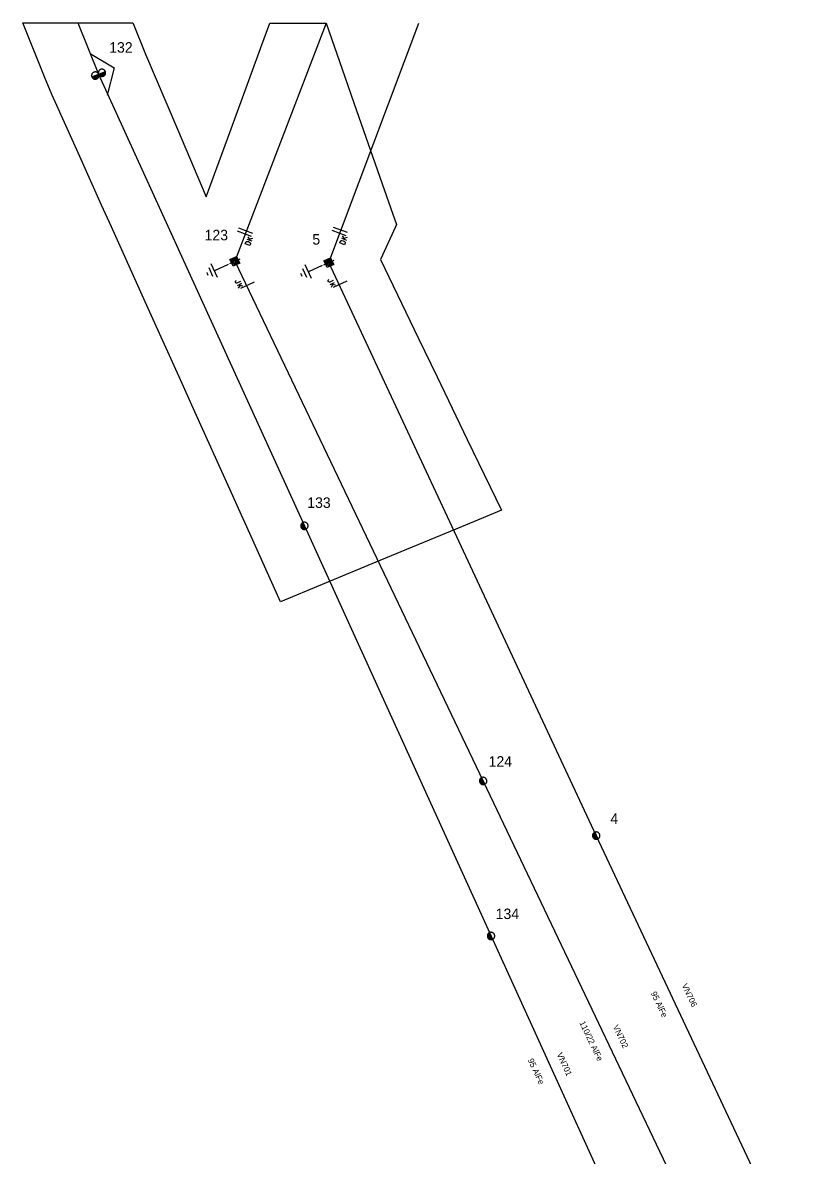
# Model space of a CAD drawing. Extents: x -536397 to -535454, y -1201642 to -1200953.
# Drawn here: x -536397 to -536267.9, y -1201142.3 to -1200953.5 of the extents above; entities that cross this region are included whole.
import ezdxf

# ---------------------------------------------------------------- set-up
doc = ezdxf.new("R2010")
doc.units = 0
for name, color, linetype in [('Vrstva 1', 7, 'Continuous'), ('Vrstva 13', 7, 'Continuous'), ('Vrstva 14', 7, 'Continuous'), ('Vrstva 15', 7, 'Continuous'), ('Vrstva 18', 7, 'Continuous'), ('Vrstva 2', 7, 'Continuous'), ('Vrstva 3', 7, 'Continuous'), ('Vrstva 35', 7, 'Continuous')]:
    doc.layers.add(name, color=color, linetype=linetype)

# ---------------------------------------------------------------- blocks, each defined once
blk = doc.blocks.new('VN850')
at = {"layer": 'Vrstva 15'}
for points in [[(-0.56, 1.43), (-0.56, -1.07)], [(-0.01, 1.43), (-0.01, -1.07)], [(-2.09, -0.54), (-1.78, -0.54)], [(-2.09, -1.41), (-2.09, -0.54)], [(-1.78, -1.41), (-2.09, -1.41)], [(-1.78, -0.54), (-1.66, -0.6)], [(-1.67, -1.35), (-1.78, -1.41)], [(-1.59, -1.2), (-1.67, -1.35)], [(-1.66, -0.6), (-1.59, -0.75)], [(-1.59, -0.75), (-1.55, -0.96)], [(-1.55, -0.96), (-1.59, -1.2)], [(-1.26, -0.54), (-1.26, -1.41)], [(-0.85, -0.54), (-1.26, -1.09)], [(-1.13, -0.92), (-0.77, -1.41)]]:
    blk.add_lwpolyline(points, dxfattribs=at)
blk = doc.blocks.new('VN840')
at = {"layer": 'Vrstva 15'}
for points in [[(-0.01, 1.41), (-0.01, -1.09)], [(-1.51, -1.24), (-1.51, -1.15)], [(-1.48, -1.35), (-1.51, -1.24)], [(-1.33, -1.42), (-1.48, -1.35)], [(-1.27, -1.42), (-1.33, -1.42)], [(-1.13, -1.35), (-1.27, -1.42)], [(-1.09, -1.24), (-1.13, -1.35)], [(-1.09, -0.59), (-1.09, -1.24)], [(-0.68, -0.59), (-0.68, -1.42)], [(-0.68, -1.11), (-0.27, -0.59)], [(-0.54, -0.94), (-0.2, -1.42)]]:
    blk.add_lwpolyline(points, dxfattribs=at)
blk = doc.blocks.new('VN860')
at = {"layer": 'Vrstva 15'}
for points in [[(-3.74, 0), (0.01, 2.82)], [(0.01, 2.82), (3.76, 0)]]:
    blk.add_lwpolyline(points, dxfattribs=at)
blk = doc.blocks.new('VN440')
at = {"layer": 'Vrstva 2'}
for points in [[(1.22, 0), (1.21, 0.13), (1.19, 0.25), (1.16, 0.38), (1.11, 0.5), (1.05, 0.61), (0.98, 0.72), (0.9, 0.82), (0.81, 0.91), (0.71, 0.99), (0.6, 1.06), (0.49, 1.12), (0.37, 1.16), (0.25, 1.2), (0.12, 1.22), (-0.01, 1.22), (-0.14, 1.22), (-0.26, 1.2), (-0.39, 1.16), (-0.51, 1.12), (-0.62, 1.06), (-0.73, 0.99), (-0.83, 0.91), (-0.92, 0.82), (-1, 0.72), (-1.07, 0.61), (-1.13, 0.5), (-1.18, 0.38), (-1.21, 0.25), (-1.23, 0.13), (-1.24, 0), (-1.23, -0.13), (-1.21, -0.26), (-1.18, -0.38), (-1.13, -0.5), (-1.07, -0.62), (-1, -0.73), (-0.92, -0.83), (-0.83, -0.92), (-0.73, -1), (-0.62, -1.07), (-0.51, -1.13), (-0.39, -1.17), (-0.26, -1.2), (-0.14, -1.23), (-0.01, -1.23), (0.12, -1.23), (0.25, -1.2), (0.37, -1.17), (0.49, -1.13), (0.6, -1.07), (0.71, -1), (0.81, -0.92), (0.9, -0.83), (0.98, -0.73), (1.05, -0.62), (1.11, -0.5), (1.16, -0.38), (1.19, -0.26), (1.21, -0.13), (1.22, 0)], [(-1.24, 0), (1.22, 0)], [(-1.18, -0.34), (1.1, -0.34)], [(-1.01, -0.63), (0.97, -0.63)], [(-0.74, -0.92), (0.68, -0.92)]]:
    blk.add_lwpolyline(points, dxfattribs=at)
blk = doc.blocks.new('VN810')
at = {"layer": 'Vrstva 14'}
for points in [[(0, -1.25), (0, -3.75)], [(1.25, -3.75), (-1.25, -3.75)], [(0.77, -4.37), (-0.8, -4.37)], [(0, -5), (-0.25, -5)], [(0.27, -5), (0, -5)]]:
    blk.add_lwpolyline(points, dxfattribs=at)
blk = doc.blocks.new('VN450')
at = {"layer": 'Vrstva 2'}
for points in [[(0, 0), (-0.01, 0.13), (-0.03, 0.25), (-0.06, 0.38), (-0.11, 0.5), (-0.16, 0.61), (-0.23, 0.72), (-0.31, 0.82), (-0.4, 0.91), (-0.5, 0.99), (-0.61, 1.06), (-0.72, 1.11), (-0.84, 1.16), (-0.97, 1.19), (-1.09, 1.21), (-1.22, 1.22), (-1.35, 1.21), (-1.47, 1.19), (-1.59, 1.16), (-1.71, 1.11), (-1.83, 1.06), (-1.93, 0.99), (-2.03, 0.91), (-2.12, 0.82), (-2.2, 0.72), (-2.27, 0.61), (-2.33, 0.5), (-2.38, 0.38), (-2.41, 0.25), (-2.43, 0.13), (-2.44, 0), (-2.43, -0.13), (-2.41, -0.25), (-2.38, -0.38), (-2.33, -0.5), (-2.27, -0.61), (-2.2, -0.72), (-2.12, -0.82), (-2.03, -0.91), (-1.93, -0.99), (-1.83, -1.06), (-1.71, -1.11), (-1.59, -1.16), (-1.47, -1.19), (-1.35, -1.21), (-1.22, -1.22), (-1.09, -1.21), (-0.97, -1.19), (-0.84, -1.16), (-0.72, -1.11), (-0.61, -1.06), (-0.5, -0.99), (-0.4, -0.91), (-0.31, -0.82), (-0.23, -0.72), (-0.16, -0.61), (-0.11, -0.5), (-0.06, -0.38), (-0.03, -0.25), (-0.01, -0.13), (0, 0)], [(-2.44, 0), (2.44, 0)], [(2.44, 0), (2.43, 0.13), (2.41, 0.25), (2.38, 0.38), (2.33, 0.5), (2.27, 0.61), (2.2, 0.72), (2.12, 0.82), (2.03, 0.91), (1.94, 0.99), (1.83, 1.06), (1.71, 1.11), (1.6, 1.16), (1.47, 1.19), (1.35, 1.21), (1.22, 1.22), (1.09, 1.21), (0.97, 1.19), (0.84, 1.16), (0.72, 1.11), (0.61, 1.06), (0.5, 0.99), (0.4, 0.91), (0.31, 0.82), (0.23, 0.72), (0.16, 0.61), (0.11, 0.5), (0.06, 0.38), (0.03, 0.25), (0.01, 0.13), (0, 0), (0.01, -0.13), (0.03, -0.25), (0.06, -0.38), (0.11, -0.5), (0.16, -0.61), (0.23, -0.72), (0.31, -0.82), (0.4, -0.91), (0.5, -0.99), (0.61, -1.06), (0.72, -1.11), (0.84, -1.16), (0.97, -1.19), (1.09, -1.21), (1.22, -1.22), (1.35, -1.21), (1.47, -1.19), (1.6, -1.16), (1.71, -1.11), (1.83, -1.06), (1.94, -0.99), (2.03, -0.91), (2.12, -0.82), (2.2, -0.72), (2.27, -0.61), (2.33, -0.5), (2.38, -0.38), (2.41, -0.25), (2.43, -0.13), (2.44, 0)], [(-2.4, -0.31), (-0.04, -0.31)], [(-2.26, -0.61), (-0.17, -0.61)], [(-2.01, -0.92), (-0.42, -0.92)], [(0.04, -0.31), (2.4, -0.31)], [(0.17, -0.61), (2.27, -0.61)], [(0.42, -0.92), (2.02, -0.92)]]:
    blk.add_lwpolyline(points, dxfattribs=at)
blk = doc.blocks.new('VN470')
at = {"layer": 'Vrstva 2'}
for points in [[(-1.23, 1.22), (1.23, 1.22)], [(-1.23, -1.23), (-1.23, 1.22)], [(-0.92, 0.9), (0.92, 0.9)], [(-0.92, -0.95), (-0.92, 0.9)], [(-0.61, 0.61), (0.61, 0.61)], [(-0.61, -0.62), (-0.61, 0.61)], [(-0.31, -0.27), (-0.31, 0.34)], [(-0.31, 0.34), (0.31, 0.34)], [(0, 1.22), (0, 1.97)], [(0.31, 0.34), (0.31, -0.27)], [(0.61, 0.61), (0.61, -0.62)], [(0.92, 0.9), (0.92, -0.95)], [(1.23, 1.22), (1.23, -1.23)], [(1.23, -1.23), (-1.23, -1.23)], [(0.92, -0.95), (-0.92, -0.95)], [(0.61, -0.62), (-0.61, -0.62)], [(0.31, -0.27), (-0.31, -0.27)], [(0, -1.23), (0, -1.98)]]:
    blk.add_lwpolyline(points, dxfattribs=at)

msp = doc.modelspace()

# ---------------------------------------------------------------- linework, layer by layer
at = {"layer": 'Vrstva 1'}
for points in [[(-536387.85, -1200953.47), (-536384.37, -1200962.05), (-536350.06, -1201037.34), (-536318.97, -1201105.71), (-536289.66, -1201170.08)], [(-536346.44, -1200953.53), (-536361.66, -1200993.24), (-536320.28, -1201079.87), (-536279.58, -1201165.38)], [(-536267.93, -1201160.31), (-536301.44, -1201088.98), (-536346, -1200993.45), (-536331, -1200953.56)]]:
    msp.add_lwpolyline(points, dxfattribs=at)
at = {"layer": 'Vrstva 35'}
msp.add_lwpolyline([(-536397.02, -1200953.46), (-536378.67, -1200953.48), (-536378.62, -1200953.62), (-536376.56, -1200958.69), (-536374.94, -1200962.5), (-536371.23, -1200971.23), (-536366.43, -1200982.52), (-536362.5, -1200971.76), (-536359.12, -1200962.5), (-536357.17, -1200957.17), (-536355.84, -1200953.52), (-536346.45, -1200953.53), (-536343.32, -1200962.5), (-536341.82, -1200966.82), (-536337.5, -1200979.22), (-536335.36, -1200985.36), (-536334.75, -1200987.12), (-536334.92, -1200987.5), (-536337.41, -1200992.96), (-536331.08, -1201006.08), (-536327.97, -1201012.5), (-536322.94, -1201022.94), (-536317.23, -1201034.75), (-536323.88, -1201037.5), (-536337.5, -1201043.14), (-536347.11, -1201047.11), (-536354.04, -1201049.98), (-536359.67, -1201037.5), (-536360.55, -1201035.55), (-536362.5, -1201031.22), (-536368.32, -1201018.32), (-536370.94, -1201012.5), (-536376.09, -1201001.09), (-536382.22, -1200987.5), (-536383.86, -1200983.86), (-536387.5, -1200975.79), (-536391.63, -1200966.63), (-536392.18, -1200965.41), (-536393.36, -1200962.5)], close=True, dxfattribs=at)

# ---------------------------------------------------------------- block references
at = {"layer": 'Vrstva 13'}
for name, p, xscale, yscale, rotation in [('VN450', (-536384.37, -1200962.05), 0.49999999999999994, 0.5000000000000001, 22.397824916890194), ('VN470', (-536361.66, -1200993.24), 0.5, 0.5, 115.29690551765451), ('VN470', (-536346, -1200993.45), 0.5, 0.5, -65.65063334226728), ('VN440', (-536350.06, -1201037.34), 0.5, 0.5, -65.50125562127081), ('VN440', (-536320.28, -1201079.87), 0.5, 0.5000000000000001, -64.46801662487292), ('VN440', (-536301.44, -1201088.98), 0.49999999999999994, 0.5000000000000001, -64.99310838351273), ('VN440', (-536318.97, -1201105.71), 0.5, 0.5, -65.54721389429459)]:
    msp.add_blockref(name, p, dxfattribs=dict(at, xscale=xscale, yscale=yscale, rotation=rotation))
at = {"layer": 'Vrstva 15'}
for p, rotation in [((-536361.66, -1200993.24), -65.24771668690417), ((-536346, -1200993.45), -65.70422495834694)]:
    msp.add_blockref('VN810', p, dxfattribs=dict(at, rotation=rotation))
at = {"layer": 'Vrstva 18'}
for name, p, rotation in [('VN860', (-536384.37, -1200962.05), -67.60193612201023), ('VN850', (-536343.96, -1200988.02), 69.3990972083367), ('VN850', (-536359.72, -1200988.17), 69.02683880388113), ('VN840', (-536359.72, -1200997.31), -64.46789164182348), ('VN840', (-536344.27, -1200997.17), -64.9932861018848)]:
    msp.add_blockref(name, p, dxfattribs=dict(at, rotation=rotation))

# ---------------------------------------------------------------- texts
at = {"layer": 'Vrstva 14'}
for s, p in [('132', (-536382.6, -1200958.46)), ('123', (-536366.71, -1200989.74)), ('5', (-536348.75, -1200990.46)), ('133', (-536349.6, -1201034.35)), ('124', (-536319.38, -1201077.48)), ('4', (-536299.09, -1201087.01)), ('134', (-536318.2, -1201102.88))]:
    msp.add_text(s, height=1.75, dxfattribs=at).set_placement(p)
at = {"layer": 'Vrstva 2'}
for s, rotation, p in [('95 AlFe', 295.164, (-536292.37, -1201115.23)), ('110/22 AlFe', 295.453, (-536304.28, -1201120.17)), ('95 AlFe', 294.481, (-536312.87, -1201126.39))]:
    msp.add_text(s, height=1, rotation=rotation, dxfattribs=at).set_placement(p)
at = {"layer": 'Vrstva 3'}
for s, rotation, p in [('VN706', 295.164, (-536287.22, -1201113.94)), ('VN702', 295.453, (-536298.7, -1201120.82)), ('VN701', 294.481, (-536308.04, -1201125.43))]:
    msp.add_text(s, height=1, rotation=rotation, dxfattribs=at).set_placement(p)

doc.saveas('drawing.dxf')
